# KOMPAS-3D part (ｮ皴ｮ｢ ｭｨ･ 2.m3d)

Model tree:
1. Эскиз:1
2. Операция вращения:1
     Угол 1 = 360
3. Эскиз:2
4. Вырезать элемент выдавливания:1
     Расстояние 1 = 30
5. Фаска:1
     Угол = 50; Длина 1 = 0.8; Длина 2 = 0.953403
